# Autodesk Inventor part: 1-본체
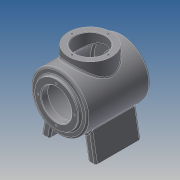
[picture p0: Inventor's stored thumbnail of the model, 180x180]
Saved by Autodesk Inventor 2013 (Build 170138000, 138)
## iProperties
Created: 2015-01
Part Number: 1-본체
Material: Generic
Document SubType Name: Modeling
Designer: kb543
Density: 1 g/cm^3
Author: kb543
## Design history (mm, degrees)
sketch "스케치1"
  geometry: L1 (-62, 0)-(60, 0); L2 (-62, 0)-(-62, 38); L3 (-62, 38)-(-57, 38); L4 (-57, 38)-(-57, 50); L5 (-57, 50)-(55, 50); L6 (55, 50)-(55, 38); L7 (55, 38)-(60, 38); L8 (60, 38)-(60, 0); L9 (-62, 27)-(-50, 27); L10 (-50, 27)-(-50, 45); L11 (-50, 45)-(47, 45); L12 (47, 45)-(47, 27); L13 (47, 27)-(60, 27); 2 further points
  constraints: 26 end point, 6 perpendicular, 5 parallel, 3 point on line, 1 coincident, 1 collinear, 1 horizontal
  dimensions: "d0" = 100 diameter of L5 L1; "d2" = 76 diameter of L3 L1; "d3" = 5 distance of L2.end L3.end; "d4" = 62 distance from line of point (0, 0) L2; "d5" = 60 distance from line of L8 point (0, 0); "d6" = 76 diameter of L7 L1 (= d2); "d7" = 5 distance of L6.end L7.end (= d3); "d10" = 54 diameter of L9 L1; "d11" = 54 diameter of L13 L1 (= d10); "d12" = 97 distance between parallel lines of L12 L10; "d13" = 7 distance between parallel lines of L10 L4; "d14" = 90 diameter of L11 L1
revolve "회전1" stored, may be unused: angle "d9" = 90 deg
revolve "회전2" stored, may be unused: angle "d15" = 90 deg
sketch "스케치3"
  geometry: L1 (-39.336, -30.865)-(-48, -80); L2 (-48, -80)-(-34, -80); L3 (-34, -80)-(-27.282, -41.901); L4 (27.282, -41.901)-(34, -80); L5 (34, -80)-(48, -80); L6 (48, -80)-(39.336, -30.865); L7 (0, 50)-(0, -50); A1 r 50 centre (0, 0) between (0, 50) and (-39.336, -30.865) reference; 2 further points
  constraints: 14 end point, 5 point on circle, 2 collinear, 1 coincident, 1 horizontal, 1 midpoint, 1 perpendicular
  dimensions: "d21" = 96 distance of L5.end L1.end; "d23" = 14 distance of L1.end L2.end; "d24" = 14 distance of L4.end L5.end (= d23); "d25" = 48 distance from line of L7 L1.end; "d26" = 80 distance from line of point (0, 0) L2; "d27" = 100 deg angle of L2 L1; "d28" = 80 deg angle of L2 L3; "d29" = 80 deg angle of L5 L4; "d30" = 100 deg angle of L5 L6
extrude "돌출1" join sketch "스케치3" stored distance "d31" = 80; taper "d32" = 0 deg
node "작업 평면2"
sketch "스케치4"
  geometry: L1 (72, 20)-(-4, 20) reference; C1 r 38 at (34, -42); 1 further point
  constraints: 1 centre point, 1 vertical alignment
  dimensions: "d34" = 62 distance from line of C1.centre L1; "d35" = 76 diameter of C1
extrude "돌출2" join sketch "스케치4" stored distance "d36" = 80; taper "d37" = 0 deg
hole "구멍1" diameter "d40" = 54; stored, may be unused: countersink angle "d44" = 90 deg, drill point angle "d46" = 118 deg; dims "d38" = 10, "d39" = 10, "d41" = 6, "d42" = 4, "d43" = 2, "d45" = 8
sketch "스케치5"
  geometry: C1 r 27 at (0, 0) reference; 5 further points
  constraints: 1 vertical alignment, 5 other
  dimensions: "d47" = 32 distance of C1.centre point (0, 32); "d50" = 360 deg dimension on C1.centre point (0, 32) (derived)
hole "구멍2" sketch "스케치5" at (0, 32), (-32, 0), (0, -32), (32, 0) diameter "d52" = 3.242; stored, may be unused: countersink angle "d56" = 90 deg, drill point angle "d58" = 118 deg; dims "d53" = 8, "d54" = 4, "d55" = 2, "d57" = 10
sketch "스케치6"
  geometry: C1 r 27 at (0, 0) reference; 4 further points
  constraints: 1 vertical alignment, 5 other
  dimensions: "d59" = 32 distance of C1.centre point (0, 32); "d62" = 360 deg dimension on C1.centre point (0, 32) (derived)
hole "구멍3" sketch "스케치6" at (0, 32), (-32, 0), (0, -32), (32, 0) diameter "d64" = 3.242; stored, may be unused: countersink angle "d68" = 90 deg, drill point angle "d70" = 118 deg; dims "d65" = 8, "d66" = 4, "d67" = 2, "d69" = 10
node "작업 평면3"
node "작업 평면5"
  node "작업 평면4"
sketch "스케치8"
  geometry: L1 (-37, 62)-(39, 62) reference; L2 (-26, 6)-(28, 6); L3 (28, 6)-(28, -6); L4 (28, -6)-(-26, -6); L5 (-26, -6)-(-26, 6); L6 (-26, 6)-(28, -6); L7 (28, 6)-(-26, -6); 5 further points
  constraints: 12 end point, 4 midpoint, 2 horizontal alignment, 2 parallel, 1 horizontal, 1 perpendicular, 1 vertical alignment
  dimensions: "d75" = 54 distance of L2.start L2.end; "d77" = 12 distance of L4.end L2.start
chamfer "모따기1" distance "d82" = 1; stored, may be unused: second distance "d83" = 2, angle "d84" = 45 deg
chamfer "모따기2" distance "d85" = 1; stored, may be unused: second distance "d86" = 2, angle "d87" = 45 deg
chamfer "모따기3" distance "d88" = 1; stored, may be unused: second distance "d89" = 2, angle "d90" = 45 deg
fillet "모깎기1" dims "d91" = 3
fillet "모깎기2" dims "d92" = 3
extrude "돌출3" join sketch "스케치8" stored distance "d93" = 80; taper "d94" = 0 deg
node "작업 평면6"
sketch "스케치10"
  geometry: L1 (-6, -28)-(-6, 26) reference; L2 (-6, 26)-(6, 26) reference; 4 further points
  constraints: 2 midpoint, 1 horizontal alignment, 1 vertical alignment, 1 other
feature "엠보싱3" sketch "스케치10" dims "d96" = 0.5, "d97" = 0
node "솔리드1"
mirror "대칭1"
other parameters: "d33" = -142, "d74" = 2, "d95" = 0.5
